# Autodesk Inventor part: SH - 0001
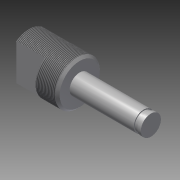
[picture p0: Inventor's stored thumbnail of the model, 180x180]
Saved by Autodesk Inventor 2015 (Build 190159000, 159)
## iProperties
Created: 2007-02
Part Number: SH - 0001
Material: Steel
Document SubType Name: Modeling
Designer: Autodesk, Inc.
Density: 7.85 g/cm^3
Description: Shaft - Fan 0062
Mass: 114.771 g
Surface Area: 43.4472 cm^2
Volume: 14.6205 cm^3
Appearance: Steel
CustomPartVersion: 1
Author: Autodesk, Inc.
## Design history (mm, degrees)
sketch "Main Sketch"
  geometry: L1 (0, 0)-(67.31, 0) reference; L2 (0, 0)-(0, 12.306); L3 (27.94, 12.306)-(27.94, 5.556); L4 (0, 12.306)-(27.94, 12.306); L5 (67.31, 5.556)-(67.31, 0); L6 (27.94, 5.556)-(67.31, 5.556)
  constraints: 12 end point, 3 horizontal, 3 vertical
  dimensions: "d3" = 24.6126 diameter of L4 L1 (derived); "d4" = 11.1125 diameter of L6 L1 (derived)
revolve "Revolution1" sketch "Main Sketch" stored, may be unused: angle "d5" = 0 deg
chamfer "Chamfer1" distance "d6" = 1.27; stored, may be unused: second distance "d7" = 3.175, angle "d8" = 45 deg
feature "iFeature7:1"
feature "iFeature27:1"
thread "Thread1" dims "d9" = 25.4, "d10" = 0
body "Solid1"
other parameters: "d0" = 0, "d1" = 0, "d2" = 0
